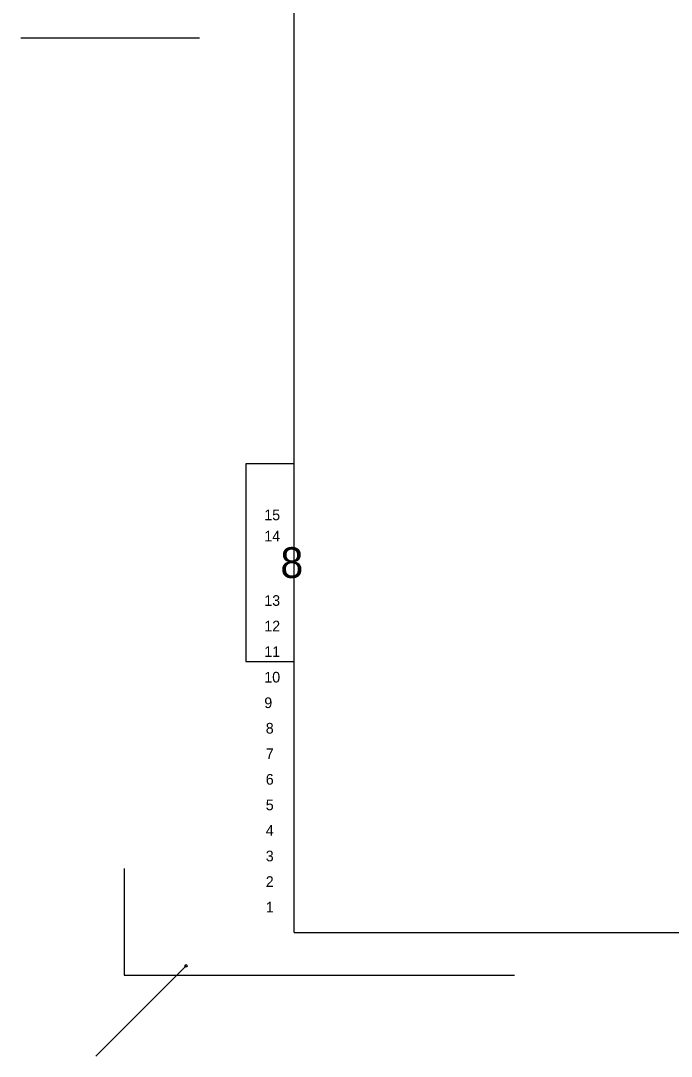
# Model space of a CAD drawing. Extents: x 997.7 to 1009.7, y 1494.3 to 1503.3.
# Drawn here: x 997.666 to 1000.213, y 1495.142 to 1499.195 of the extents above; entities that cross this region are included whole.
import ezdxf

# ---------------------------------------------------------------- set-up
doc = ezdxf.new("R2010")
doc.units = 0
for name, color, linetype in [('Level 1', 7, 'Continuous'), ('Level 10', 7, 'Continuous'), ('Level 11', 7, 'Continuous'), ('Level 12', 7, 'Continuous'), ('Level 13', 7, 'Continuous'), ('Level 14', 7, 'Continuous'), ('Level 15', 7, 'Continuous'), ('Level 2', 7, 'Continuous'), ('Level 3', 7, 'Continuous'), ('Level 37', 7, 'Continuous'), ('Level 4', 7, 'Continuous'), ('Level 49', 7, 'Continuous'), ('Level 5', 7, 'Continuous'), ('Level 6', 7, 'Continuous'), ('Level 7', 7, 'Continuous'), ('Level 8', 7, 'Continuous'), ('Level 9', 7, 'Continuous')]:
    doc.layers.add(name, color=color, linetype=linetype)

msp = doc.modelspace()

# ---------------------------------------------------------------- linework, layer by layer
at = {"layer": 'Level 1'}
for p, q in [((998.7369, 1495.6261), (998.7369, 1502.6253)), ((998.0703, 1495.8769), (998.0703, 1495.4594)), ((998.7369, 1495.6261), (1009.1944, 1495.6261)), ((998.0703, 1495.4594), (999.5995, 1495.4594))]:
    msp.add_line(p, q, dxfattribs=at)
msp.add_lwpolyline([(998.7369, 1497.4608), (998.5478, 1497.4608), (998.5478, 1496.6871), (998.7369, 1496.6871)], close=True, dxfattribs=at)
at = {"layer": 'Level 2'}
msp.add_line((997.9595, 1495.1423), (998.3131, 1495.4958), dxfattribs=at)
at = {"layer": 'Level 37'}
msp.add_line((998.3654, 1499.1256), (997.6658, 1499.1256), dxfattribs=at)
at = {"layer": 'Level 49'}
msp.add_circle((998.313, 1495.4958), 0.00506, dxfattribs=at)

# ---------------------------------------------------------------- texts
at = {"layer": 'Level 1'}
for s, height, p in [('8', 0.1204, (998.6826, 1497.0138)), ('1', 0.0417, (998.6253, 1495.7051))]:
    msp.add_text(s, height=height, dxfattribs=at).set_placement(p)
at = {"layer": 'Level 10'}
msp.add_text('10', height=0.04167, dxfattribs=at).set_placement((998.6195, 1496.6049))
at = {"layer": 'Level 11'}
msp.add_text('11', height=0.04167, dxfattribs=at).set_placement((998.6195, 1496.7049))
at = {"layer": 'Level 12'}
msp.add_text('12', height=0.04167, dxfattribs=at).set_placement((998.6195, 1496.8049))
at = {"layer": 'Level 13'}
msp.add_text('13', height=0.04167, dxfattribs=at).set_placement((998.6195, 1496.9049))
at = {"layer": 'Level 14'}
msp.add_text('14', height=0.04167, dxfattribs=at).set_placement((998.6195, 1497.1569))
at = {"layer": 'Level 15'}
msp.add_text('15', height=0.04167, dxfattribs=at).set_placement((998.6195, 1497.2398))
at = {"layer": 'Level 2'}
msp.add_text('2', height=0.0417, dxfattribs=at).set_placement((998.6253, 1495.8051))
at = {"layer": 'Level 3'}
msp.add_text('3', height=0.0417, dxfattribs=at).set_placement((998.6253, 1495.9051))
at = {"layer": 'Level 4'}
msp.add_text('4', height=0.0417, dxfattribs=at).set_placement((998.6253, 1496.0051))
at = {"layer": 'Level 5'}
msp.add_text('5', height=0.0417, dxfattribs=at).set_placement((998.6253, 1496.1051))
at = {"layer": 'Level 6'}
msp.add_text('6', height=0.0417, dxfattribs=at).set_placement((998.6253, 1496.2051))
at = {"layer": 'Level 7'}
msp.add_text('7', height=0.0417, dxfattribs=at).set_placement((998.6253, 1496.3051))
at = {"layer": 'Level 8'}
msp.add_text('8', height=0.0417, dxfattribs=at).set_placement((998.6253, 1496.4051))
at = {"layer": 'Level 9'}
msp.add_text('9', height=0.0417, dxfattribs=at).set_placement((998.6195, 1496.5049))

doc.saveas('drawing.dxf')
